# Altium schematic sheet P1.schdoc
size 297 x 209 mm; Company: 嘉立创EDA; Version: V1.0; Page Size: A4; @Project Name: 水墨屏demo1; @Page Count: 1; @Update Date: 2026-05-06; @Create Date: 2026-02-25; @Schematic Name: 总层次原理图; @Page No: 0; @Page Name: P1; @Board Name: 1_总层次原理图; Border: 1; Title Block Position: 3; Size: A4; Width: 1170; Height: 825; Region Start: 1; X Region Count: 6; Y Region Count: 4; Blade Width: 10; Device: Drawing-Symbol_A4
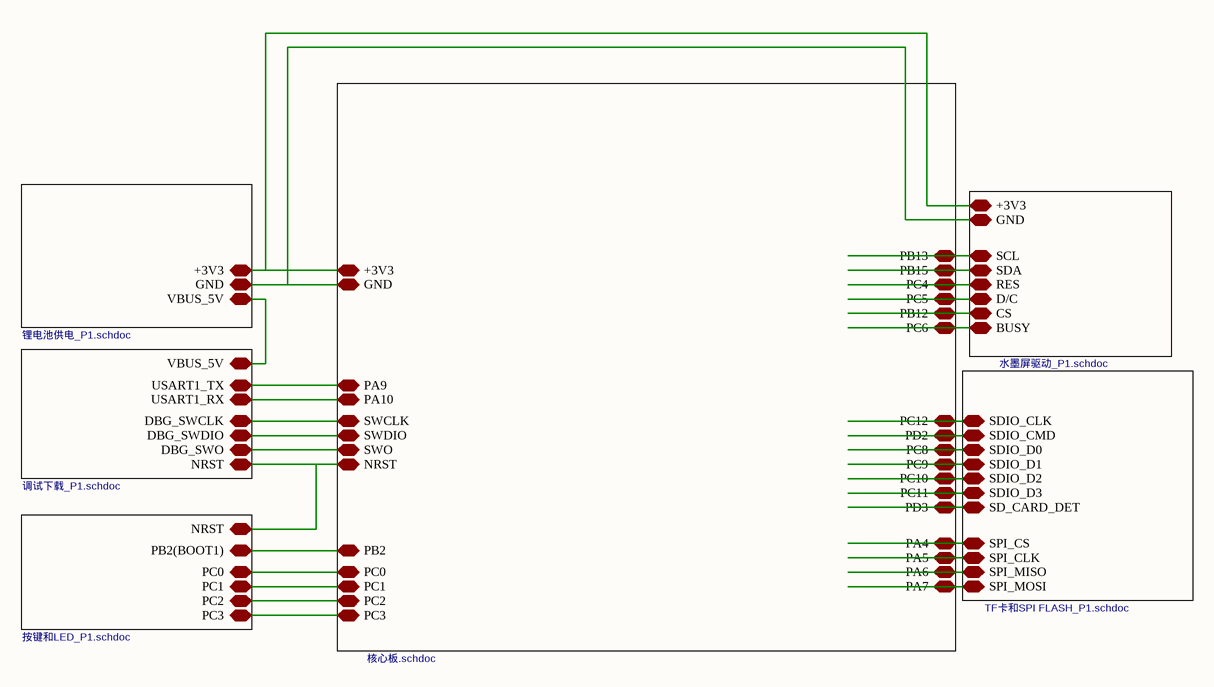
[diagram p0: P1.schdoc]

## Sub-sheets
CBB1 = 核心板.schdoc: GND, +3V3, PD3, PD2, PB2, PC12, PC11, PC10, PC9, PC8, PA10, PA9, PA7, PA6, PA5, PA4, SWDIO, SWO, NRST, SWCLK, PC0, PC1, PC2, PC3, PB13, PB15, PC4, PC5, PB12, PC6  | Symbol: stm32F407最小系统
CBB3 = 调试下载_P1.schdoc: NRST, DBG_SWO, DBG_SWDIO, DBG_SWCLK, USART1_TX, USART1_RX, VBUS_5V  | Symbol: 调试下载
CBB4 = TF卡和SPI FLASH_P1.schdoc: SDIO_D3, SDIO_D2, SDIO_D1, SDIO_D0, SPI_MISO, SD_CARD_DET, SPI_CLK, SPI_MOSI, SPI_CS, SDIO_CMD, SDIO_CLK  | Symbol: TF卡和SPI FLASH
CBB5 = 按键和LED_P1.schdoc: NRST, PC0, PB2(BOOT1), PC1, PC2, PC3  | Symbol: 按键和LED
CBB6 = 水墨屏驱动_P1.schdoc: +3V3, GND, SCL, SDA, RES, D/C, CS, BUSY  | Symbol: 水墨屏驱动
CBB7 = 锂电池供电_P1.schdoc: +3V3, GND, VBUS_5V  | Symbol: 锂电池供电

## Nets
(unnamed): sheet CBB1/GND, sheet CBB6/GND, sheet CBB7/GND
(unnamed): sheet CBB1/+3V3, sheet CBB6/+3V3, sheet CBB7/+3V3  [a separate net that carries the same name]
(unnamed): sheet CBB1/PD3, sheet CBB4/SD_CARD_DET  [a separate net that carries the same name]
(unnamed): sheet CBB1/PD2, sheet CBB4/SDIO_CMD  [a separate net that carries the same name]
(unnamed): sheet CBB1/PB2, sheet CBB5/PB2(BOOT1)  [a separate net that carries the same name]
(unnamed): sheet CBB1/PC12, sheet CBB4/SDIO_CLK  [a separate net that carries the same name]
(unnamed): sheet CBB1/PC11, sheet CBB4/SDIO_D3  [a separate net that carries the same name]
(unnamed): sheet CBB1/PC10, sheet CBB4/SDIO_D2  [a separate net that carries the same name]
(unnamed): sheet CBB1/PC9, sheet CBB4/SDIO_D1  [a separate net that carries the same name]
(unnamed): sheet CBB1/PC8, sheet CBB4/SDIO_D0  [a separate net that carries the same name]
(unnamed): sheet CBB1/PA10, sheet CBB3/USART1_RX  [a separate net that carries the same name]
(unnamed): sheet CBB1/PA9, sheet CBB3/USART1_TX  [a separate net that carries the same name]
(unnamed): sheet CBB1/PA7, sheet CBB4/SPI_MOSI  [a separate net that carries the same name]
(unnamed): sheet CBB1/PA6, sheet CBB4/SPI_MISO  [a separate net that carries the same name]
(unnamed): sheet CBB1/PA5, sheet CBB4/SPI_CLK  [a separate net that carries the same name]
(unnamed): sheet CBB1/PA4, sheet CBB4/SPI_CS  [a separate net that carries the same name]
(unnamed): sheet CBB1/SWDIO, sheet CBB3/DBG_SWDIO  [a separate net that carries the same name]
(unnamed): sheet CBB1/SWO, sheet CBB3/DBG_SWO  [a separate net that carries the same name]
(unnamed): sheet CBB1/NRST, sheet CBB3/NRST, sheet CBB5/NRST  [a separate net that carries the same name]
(unnamed): sheet CBB1/SWCLK, sheet CBB3/DBG_SWCLK  [a separate net that carries the same name]
(unnamed): sheet CBB1/PC0, sheet CBB5/PC0  [a separate net that carries the same name]
(unnamed): sheet CBB1/PC1, sheet CBB5/PC1  [a separate net that carries the same name]
(unnamed): sheet CBB1/PC2, sheet CBB5/PC2  [a separate net that carries the same name]
(unnamed): sheet CBB1/PC3, sheet CBB5/PC3  [a separate net that carries the same name]
(unnamed): sheet CBB1/PB13, sheet CBB6/SCL  [a separate net that carries the same name]
(unnamed): sheet CBB1/PB15, sheet CBB6/SDA  [a separate net that carries the same name]
(unnamed): sheet CBB1/PC4, sheet CBB6/RES  [a separate net that carries the same name]
(unnamed): sheet CBB1/PC5, sheet CBB6/D/C  [a separate net that carries the same name]
(unnamed): sheet CBB1/PB12, sheet CBB6/CS  [a separate net that carries the same name]
(unnamed): sheet CBB1/PC6, sheet CBB6/BUSY  [a separate net that carries the same name]
(unnamed): sheet CBB3/VBUS_5V, sheet CBB7/VBUS_5V  [a separate net that carries the same name]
